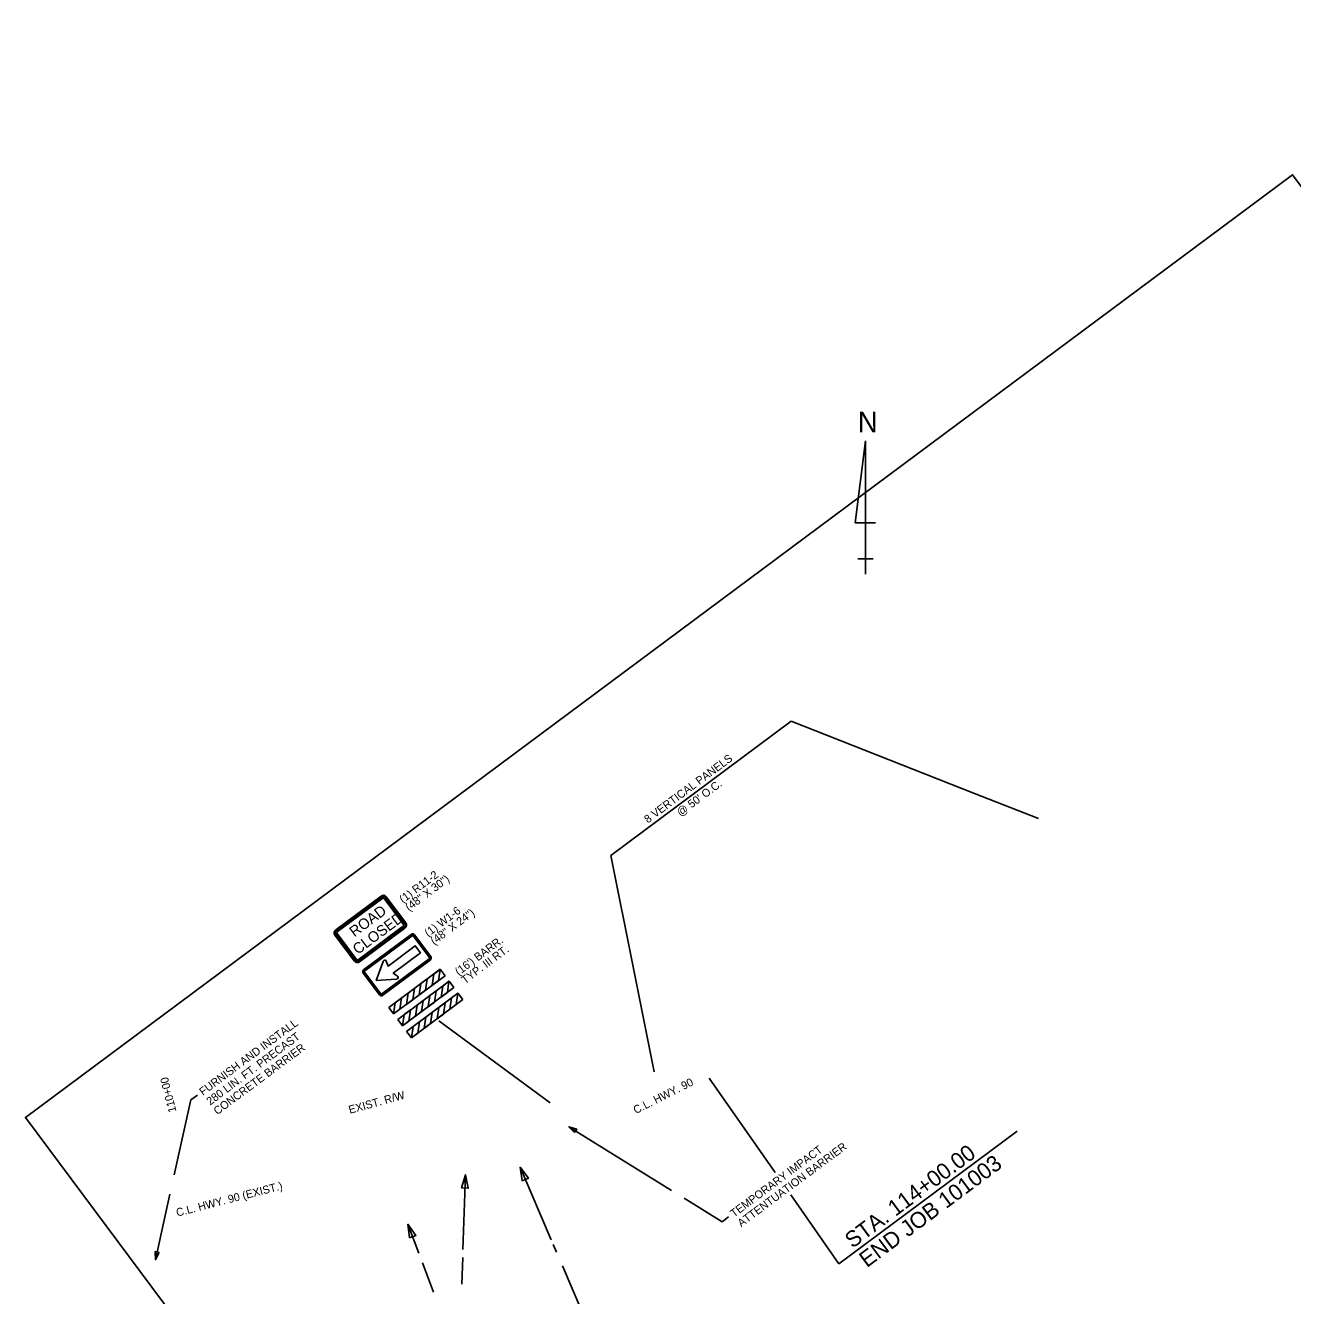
# Model space of a CAD drawing. Extents: x 1571137 to 1573037, y 731597 to 733451.
# Drawn here: x 1571137 to 1572087, y 732297 to 733249 of the extents above; entities that cross this region are included whole.
import ezdxf

# ---------------------------------------------------------------- set-up
doc = ezdxf.new("R2010")
doc.units = 0
for name, color, linetype in [('Level 3', 7, 'Continuous'), ('P_TC_Signs_Permanent', 7, 'Continuous'), ('R_Annotation', 7, 'Continuous'), ('R_Horz Alg Annot', 7, 'Continuous'), ('R_Proposed Road_Lane', 7, 'Continuous'), ('R_ROW Annot', 7, 'Continuous')]:
    doc.layers.add(name, color=color, linetype=linetype)

msp = doc.modelspace()

# ---------------------------------------------------------------- linework, layer by layer
at = {"layer": 'Level 3'}
for p, q in [((1571447.91, 732541.36), (1571409.38, 732512.68)), ((1571451.51, 732536.52), (1571412.98, 732507.85)), ((1571451.51, 732536.52), (1571447.91, 732541.36)), ((1571454.58, 732532.39), (1571416.06, 732503.72)), ((1571458.17, 732527.57), (1571419.65, 732498.89)), ((1571458.17, 732527.57), (1571454.58, 732532.39)), ((1571461.24, 732523.45), (1571422.71, 732494.78)), ((1571464.83, 732518.63), (1571426.3, 732489.96)), ((1571464.83, 732518.63), (1571461.24, 732523.45)), ((1571412.98, 732507.85), (1571409.38, 732512.68)), ((1571413, 732507.88), (1571412.95, 732507.89)), ((1571419.65, 732498.89), (1571416.06, 732503.72)), ((1571419.65, 732498.89), (1571416.06, 732503.72)), ((1571426.3, 732489.96), (1571422.71, 732494.78))]:
    msp.add_line(p, q, dxfattribs=at)
for points in [[(1571432.25, 732522.16), (1571436.97, 732525.7), (1571438.2, 732534.09), (1571433.48, 732530.57)], [(1571441.88, 732529.33), (1571446.6, 732532.86), (1571447.83, 732541.25), (1571443.11, 732537.74)], [(1571422.62, 732515), (1571427.35, 732518.54), (1571428.58, 732526.92), (1571423.86, 732523.41)], [(1571438.9, 732513.22), (1571443.63, 732516.76), (1571444.86, 732525.15), (1571440.13, 732521.63)], [(1571448.53, 732520.39), (1571453.25, 732523.93), (1571454.48, 732532.31), (1571449.76, 732528.8)], [(1571413, 732507.83), (1571417.72, 732511.37), (1571418.95, 732519.76), (1571414.23, 732516.24)], [(1571429.27, 732506.06), (1571434, 732509.6), (1571435.23, 732517.98), (1571430.51, 732514.47)], [(1571445.57, 732504.26), (1571450.3, 732507.79), (1571451.53, 732516.18), (1571446.81, 732512.67)], [(1571455.2, 732511.42), (1571459.93, 732514.96), (1571461.16, 732523.35), (1571456.43, 732519.83)], [(1571419.65, 732498.89), (1571424.37, 732502.43), (1571425.6, 732510.82), (1571420.88, 732507.31)], [(1571435.95, 732497.09), (1571440.67, 732500.63), (1571441.9, 732509.02), (1571437.18, 732505.5)], [(1571426.32, 732489.93), (1571431.05, 732493.47), (1571432.28, 732501.85), (1571427.55, 732498.34)]]:
    msp.add_lwpolyline(points, close=True, dxfattribs=at)
at = {"layer": 'P_TC_Signs_Permanent'}
for p, q in [((1571403.58, 732596.27), (1571369.57, 732570.96)), ((1571404.06, 732595.63), (1571370.05, 732570.32)), ((1571404.78, 732594.67), (1571370.76, 732569.35)), ((1571420.46, 732574.93), (1571405.9, 732594.5)), ((1571421.43, 732575.64), (1571406.86, 732595.22)), ((1571422.07, 732576.12), (1571407.5, 732595.7)), ((1571386.29, 732548.49), (1571420.3, 732573.81)), ((1571387, 732547.53), (1571421.02, 732572.85)), ((1571387.48, 732546.89), (1571421.49, 732572.2)), ((1571368.99, 732567.04), (1571383.56, 732547.46)), ((1571369.64, 732567.52), (1571384.2, 732547.94)), ((1571370.6, 732568.23), (1571385.17, 732548.66)), ((1571426.13, 732567.53), (1571390.63, 732541.11)), ((1571426.43, 732567.13), (1571390.93, 732540.71)), ((1571426.87, 732566.53), (1571391.38, 732540.11)), ((1571439.84, 732550.15), (1571427.75, 732566.4)), ((1571440.44, 732550.6), (1571428.35, 732566.85)), ((1571440.84, 732550.9), (1571428.75, 732567.14)), ((1571404.21, 732522.86), (1571439.71, 732549.28)), ((1571404.66, 732522.26), (1571440.16, 732548.68)), ((1571404.96, 732521.86), (1571440.46, 732548.28)), ((1571390.24, 732538.49), (1571402.33, 732522.24)), ((1571390.65, 732538.78), (1571402.74, 732522.54)), ((1571391.25, 732539.23), (1571403.34, 732522.99))]:
    msp.add_line(p, q, dxfattribs=at)
for points in [[(1571415.87, 732536.1), (1571412.66, 732538.5), (1571433.13, 732553.73), (1571429.25, 732558.94), (1571408.78, 732543.71), (1571407.43, 732547.48)], [(1571405.1, 732547.26), (1571399.9, 732533.05), (1571415, 732533.98)]]:
    msp.add_lwpolyline(points, dxfattribs=at)
for centre, radius, start, end in [((1571405.26, 732594.02), 2.8, 36.65758, 126.65758), ((1571405.26, 732594.02), 2, 36.65758, 126.65758), ((1571405.26, 732594.02), 0.8, 36.65758, 126.65758), ((1571419.82, 732574.45), 0.8, 306.65758, 36.65758), ((1571419.82, 732574.45), 2, 306.65758, 36.65758), ((1571419.82, 732574.45), 2.8, 306.65758, 36.65758), ((1571371.24, 732568.71), 2.8, 126.65758, 216.65758), ((1571371.24, 732568.71), 2, 126.65758, 216.65758), ((1571371.24, 732568.71), 0.8, 126.65758, 216.65758), ((1571427.25, 732566.02), 1.87, 36.65758, 126.65758), ((1571427.25, 732566.02), 1.38, 36.65758, 126.65758), ((1571427.25, 732566.02), 0.625, 36.65758, 126.65758), ((1571385.81, 732549.14), 2.8, 216.65758, 306.65758), ((1571385.81, 732549.14), 2, 216.65758, 306.65758), ((1571385.81, 732549.14), 0.8, 216.65758, 306.65758), ((1571358.15, 732564.46), 50, 339.88618, 340.13306), ((1571406.31, 732547.06), 1.2, 20.68851, 160.13306), ((1571439.34, 732549.78), 0.625, 306.65758, 36.65758), ((1571439.34, 732549.78), 1.37, 306.65758, 36.65758), ((1571439.34, 732549.78), 1.88, 306.65758, 36.65758), ((1571391.75, 732539.61), 1.88, 126.65758, 216.65758), ((1571391.75, 732539.61), 1.38, 126.65758, 216.65758), ((1571391.75, 732539.61), 0.625, 126.65758, 216.65758), ((1571415.16, 732535.17), 1.18, 273.25701, 52.62666), ((1571418.07, 732484.07), 50, 93.25701, 93.51455), ((1571403.84, 732523.36), 1.87, 216.65758, 306.65758), ((1571403.84, 732523.36), 1.38, 216.65758, 306.65758), ((1571403.84, 732523.36), 0.625, 216.65758, 306.65758)]:
    msp.add_arc(centre, radius, start, end, dxfattribs=at)
at = {"layer": 'R_Annotation'}
for p, q in [((1571575.72, 732626.74), (1571710.93, 732727.48)), ((1571848.36, 732673.27), (1571710.93, 732727.48)), ((1571896.33, 732654.35), (1571848.36, 732673.27)), ((1571592.72, 732542), (1571575.72, 732626.74)), ((1571608.3, 732464.41), (1571592.72, 732542)), ((1571530.32, 732441.26), (1571446.81, 732502.79)), ((1571649.45, 732459.67), (1571698.94, 732388.93)), ((1571248.54, 732387.17), (1571261.04, 732443.34)), ((1571265.86, 732446.92), (1571261.04, 732443.34)), ((1571880.28, 732419.94), (1571746.76, 732320.58)), ((1571507.83, 732392.92), (1571531.16, 732338.39)), ((1571466.79, 732387.28), (1571464.94, 732331.18)), ((1571234.37, 732323.49), (1571245.3, 732372.59)), ((1571710.63, 732372.23), (1571746.76, 732320.58)), ((1571423.72, 732350.17), (1571431.88, 732328.56)), ((1571532.6, 732335.01), (1571535.04, 732329.3)), ((1571464.75, 732325.28), (1571464.09, 732305.26)), ((1571434.65, 732321.24), (1571442.96, 732299.21)), ((1571539.47, 732318.97), (1571576.97, 732231.31))]:
    msp.add_line(p, q, dxfattribs=at)
for points in [[(1571509.46, 732382.74), (1571507.83, 732392.92), (1571514.06, 732384.71)], [(1571463.96, 732377.37), (1571466.79, 732387.28), (1571468.96, 732377.2)], [(1571424.91, 732339.93), (1571423.72, 732350.17), (1571429.59, 732341.7)], [(1571237.14, 732329.02), (1571234.37, 732323.49), (1571234.21, 732329.67)]]:
    msp.add_lwpolyline(points, close=True, dxfattribs=at)
at = {"layer": 'R_Horz Alg Annot'}
msp.add_lwpolyline([(1572536.74, 733221.56), (1573036.71, 732549.76), (1571756.88, 731597.29), (1571136.98, 732430.24), (1572086.85, 733137.16), (1572116.34, 733097.53), (1572258.81, 733203.56), (1572269.47, 733189.25), (1572284.07, 733200.11), (1572282.13, 733202.72), (1572344.44, 733249.09)], dxfattribs=at)
at = {"layer": 'R_Proposed Road_Lane'}
for p, q in [((1571766.62, 732937.58), (1571758.93, 732876.04)), ((1571766.62, 732837.58), (1571766.62, 732937.58)), ((1571766.62, 732937.58), (1571766.62, 732860.65)), ((1571758.93, 732876.04), (1571774.31, 732876.04)), ((1571766.62, 732837.58), (1571766.62, 732860.65)), ((1571766.62, 732849.11), (1571760.85, 732849.11)), ((1571760.85, 732849.11), (1571772.39, 732849.11)), ((1571766.62, 732837.58), (1571766.62, 732849.11)), ((1571544.39, 732423.31), (1571621.37, 732375.51)), ((1571630.84, 732369.63), (1571659.14, 732352.06)), ((1571663.96, 732355.64), (1571659.14, 732352.06))]:
    msp.add_line(p, q, dxfattribs=at)
msp.add_lwpolyline([(1571548.69, 732418.87), (1571544.39, 732423.31), (1571550.27, 732421.42)], close=True, dxfattribs=at)

# ---------------------------------------------------------------- texts
at = {"layer": 'P_TC_Signs_Permanent'}
for s, p in [('ROAD', (1571383.62, 732565.21)), ('CLOSED', (1571386.07, 732552.07))]:
    msp.add_text(s, height=8, rotation=36.65758, dxfattribs=at).set_placement(p)
at = {"layer": 'R_Annotation'}
for s, height, rotation, p in [('8 VERTICAL PANELS ', 6, 36.65758, (1571603.55, 732650.59)), ("@ 50' O.C. ", 6, 36.65758, (1571627.97, 732655.67)), ('(1) R11-2', 6, 36.8295, (1571420.02, 732590.67)), ('(48" X 30")', 6, 36.8295, (1571424.52, 732584.66)), ('(1) W1-6 ', 6, 36.81334, (1571438.88, 732565.32)), ('(48" X 24")', 6, 36.81334, (1571443.38, 732559.31)), ("(16') BARR.", 6, 36.8295, (1571461.71, 732536.38)), ('TYP. III RT.', 6, 36.8295, (1571466.5, 732529.99)), ('FURNISH AND INSTALL ', 6, 36.65758, (1571270.06, 732446.31)), ('280 LIN. FT. PRECAST ', 6, 36.65758, (1571275.43, 732439.09)), ('CONCRETE BARRIER', 6, 36.65758, (1571280.8, 732431.87)), ('C.L. HWY. 90', 6, 26.76477, (1571594.51, 732432.68)), ('STA. 114+00.00', 12, 36.65758, (1571756.96, 732331.67)), ('END JOB 101003', 12, 36.65758, (1571767.7, 732317.23)), ('C.L. HWY. 90 (EXIST.)', 6, 14.51327, (1571250.82, 732355.83))]:
    msp.add_text(s, height=height, rotation=rotation, dxfattribs=at).set_placement(p)
at = {"layer": 'R_Horz Alg Annot'}
msp.add_text('110+00', height=6, rotation=103.97725, dxfattribs=at).set_placement((1571250.22, 732434.78))
at = {"layer": 'R_Proposed Road_Lane'}
msp.add_text('N', height=15.38, dxfattribs=at).set_placement((1571760.99, 732943.99))
for s, p in [('ATTENTUATION BARRIER', (1571673.53, 732347.81)), ('TEMPORARY IMPACT', (1571668.15, 732355.03))]:
    msp.add_text(s, height=6, rotation=36.65758, dxfattribs=at).set_placement(p)
at = {"layer": 'R_ROW Annot'}
msp.add_text('EXIST. R/W', height=6, rotation=15.41249, dxfattribs=at).set_placement((1571380.18, 732432.94))

doc.saveas('drawing.dxf')
